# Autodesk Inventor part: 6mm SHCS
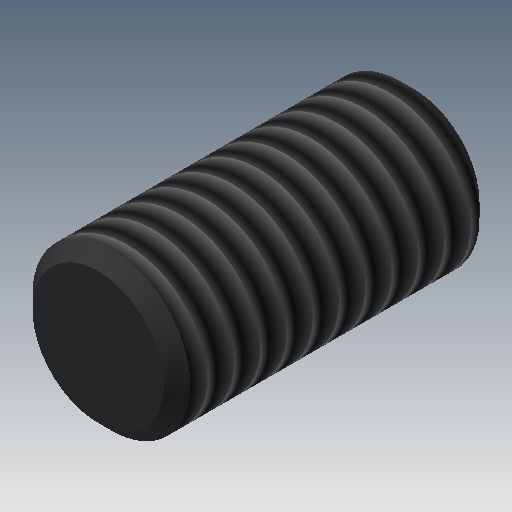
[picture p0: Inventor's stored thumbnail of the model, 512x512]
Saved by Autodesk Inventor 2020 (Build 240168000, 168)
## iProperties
Created: 2002-07
Part Number: 6mm SHCS
Description: 6mm SHCS
Document SubType Name: Modeling
Designer: PN
Density: 1 g/cm^3
Material: Generic
Appearance: 78,78,78
Control State: 0
Master: False
Checked Out: False
Shininess: 64.0
Angle Display Precision: 2
Document Length Units: 11269
Document Angle Units: 11279
Document Time Units: 11290
Document Mass Units: 11283
Document Length Units Precision: 3
Document Angle Units Precision: 2
Compacted: True
Density: 0.0
Volumn: 0.0
Area: 0.0
PropertySet Name: Model Information
Author: PN
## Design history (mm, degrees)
sketch "Sketch1"
  geometry: C1 r 3 at (0, 0); 1 further point
  constraints: 1 centre point, 1 coincident
  dimensions: "d0" = 6 diameter of C1
extrude "Extrusion1" new body sketch "Sketch1" stored distance "d1" = 12; taper "d2" = 0 deg
chamfer "Chamfer1" distance "d3" = 0.5; stored, may be unused: second distance "d4" = 0.5, angle "d21" = 45 deg
sketch "Sketch2"
  geometry: L1 (-1, 1.5)-(-1.866, 0); L2 (1, 1.5)-(-1, 1.5); L3 (-1.866, 0)-(-1, -1.5); L4 (-1, -1.5)-(1, -1.5); L5 (1.866, 0)-(1, 1.5); L6 (1, -1.5)-(1.866, 0); C1 r 2.5 at (0, 0) reference; C2 r 1.616 at (0, 0)
  constraints: 12 end point, 4 tangent, 3 parallel, 1 centre point, 1 coincident, 1 horizontal
  dimensions: "d5" = 3.23205 diameter of C2; "d10" = 1.5 distance from line of C1.centre L2; "d11" = 120 deg angle of L4 L3; "d13" = 120 deg angle of L4 L6; "d16" = 3 distance between parallel lines of L4 L2
extrude "Extrusion2" cut sketch "Sketch2" distance "d17" = 4; taper "d18" = 0 deg
thread "Thread1" dims "d19" = 10, "d20" = 0
body "Solid1"
